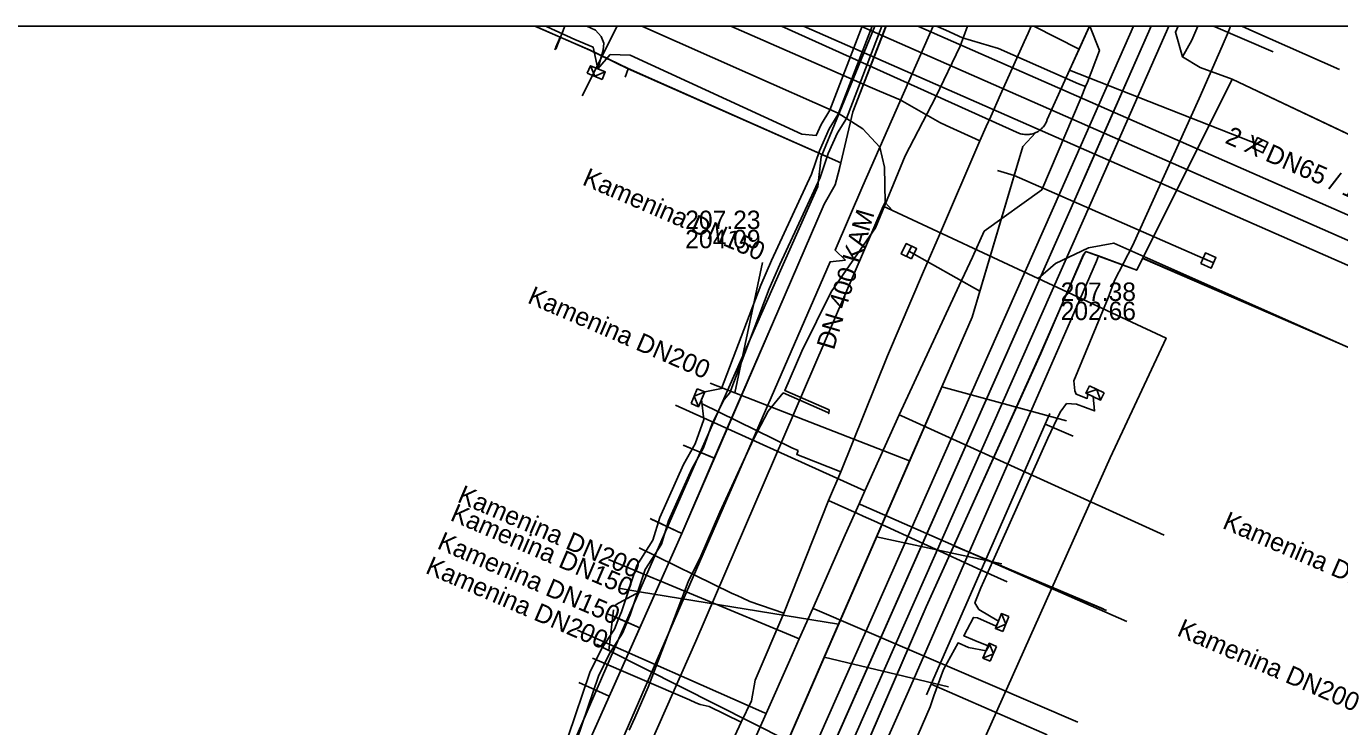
# Model space of a CAD drawing. Extents: x -596024 to -594475, y -1163820 to -1161957.
# Drawn here: x -595846.1 to -595789, y -1161987.3 to -1161956.9 of the extents above; entities that cross this region are included whole.
import ezdxf

# ---------------------------------------------------------------- set-up
doc = ezdxf.new("R2010")
doc.units = 0
for name, color, linetype in [('31', 7, 'Continuous'), ('Level 1', 7, 'Continuous'), ('Vrstva 1', 7, 'Continuous'), ('Vrstva 10', 7, 'Continuous'), ('Vrstva 12', 7, 'Continuous'), ('Vrstva 13', 7, 'Continuous'), ('Vrstva 16', 7, 'Continuous'), ('Vrstva 25', 7, 'Continuous'), ('Vrstva 3', 7, 'Continuous'), ('Vrstva 37', 7, 'Continuous'), ('Vrstva 38', 7, 'Continuous'), ('Vrstva 41', 7, 'Continuous'), ('Vrstva 42', 7, 'Continuous'), ('Vrstva 43', 7, 'Continuous'), ('Vrstva 44', 7, 'Continuous'), ('Vrstva 55', 7, 'Continuous'), ('Vrstva 63', 7, 'Continuous'), ('Vrstva 9', 7, 'Continuous')]:
    doc.layers.add(name, color=color, linetype=linetype)

# ---------------------------------------------------------------- blocks, each defined once
blk = doc.blocks.new('NN630')
at = {"layer": '31'}
for points in [[(-0.003, -0.7), (-0.703, 0)], [(-0.703, -0.7), (-0.703, 0), (0.697, 0), (0.697, -0.7)], [(-0.003, -0.7), (0.697, 0)], [(-0.703, -0.7), (0.697, -0.7)]]:
    blk.add_lwpolyline(points, dxfattribs=at)

msp = doc.modelspace()

# ---------------------------------------------------------------- linework, layer by layer
at = {"layer": 'Level 1'}
msp.add_line((-595802.331, -1161956.88), (-595800.365, -1161957.873), dxfattribs=at)
for points in [[(-595857.91, -1162093.25), (-595857.56, -1162092.36), (-595828.59, -1162027.72), (-595816.316, -1162000), (-595800.5, -1161964.28), (-595800, -1161963.147), (-595797.235, -1161956.88)], [(-595799.915, -1161956.88), (-595800, -1161957.068), (-595801.75, -1161960.93)], [(-595800.778, -1161958.784), (-595792.493, -1161962.047)], [(-595861.01, -1162094.34), (-595840.98, -1162050.22), (-595835.296, -1162037.702), (-595840.98, -1162050.22), (-595820.05, -1162004.1), (-595818.268, -1162000), (-595805.02, -1161969.52), (-595802.82, -1161962.1)], [(-595803.196, -1161963.363), (-595794.753, -1161967.058)], [(-595804.684, -1161968.388), (-595807.765, -1161966.655)]]:
    msp.add_lwpolyline(points, dxfattribs=at)
at = {"layer": 'Vrstva 1'}
msp.add_line((-595802.331, -1161956.88), (-595800.365, -1161957.873), dxfattribs=at)
for points in [[(-595792.493, -1161962.047), (-595800.778, -1161958.784)], [(-595794.753, -1161967.058), (-595803.196, -1161963.363)], [(-595807.765, -1161966.655), (-595804.684, -1161968.388)]]:
    msp.add_lwpolyline(points, dxfattribs=at)
at = {"layer": 'Vrstva 10'}
for p, q in [((-595801.14, -1161963.997), (-595798, -1161956.88)), ((-595796.47, -1161956.88), (-595799.86, -1161964.563)), ((-595829.23, -1162027.437), (-595801.14, -1161963.997)), ((-595799.86, -1161964.563), (-595827.95, -1162028.003))]:
    msp.add_line(p, q, dxfattribs=at)
at = {"layer": 'Vrstva 12'}
for p, q in [((-595822.92, -1161957.36), (-595824.015, -1161956.88)), ((-595819.366, -1161956.88), (-595814.76, -1161958.92))]:
    msp.add_line(p, q, dxfattribs=at)
for points in [[(-595810.52, -1161967.04), (-595810.97, -1161966.6), (-595809.77, -1161963.81), (-595806.71, -1161956.88)], [(-595808.757, -1161956.88), (-595810.2, -1161960.6), (-595810.72, -1161962.82)], [(-595796.064, -1161956.88), (-595796.18, -1161957.14), (-595795.87, -1161958.21)], [(-595795.87, -1161958.21), (-595795.47, -1161957.48), (-595795.209, -1161956.88)], [(-595823.15, -1161957.9), (-595822.92, -1161957.36)], [(-595810.72, -1161962.82), (-595819.97, -1161958.72), (-595821.62, -1161957.92), (-595822.79, -1161957.41), (-595822.92, -1161957.36)], [(-595795.87, -1161958.21), (-595795.1, -1161958.67), (-595793.71, -1161959.18)], [(-595814.76, -1161958.92), (-595810.84, -1161960.65), (-595809.77, -1161961.34), (-595809.02, -1161962.13), (-595808.83, -1161963), (-595808.8, -1161964.53)], [(-595793.71, -1161959.18), (-595794.49, -1161960.72), (-595797.41, -1161966.57), (-595797.6, -1161966.96)], [(-595793.71, -1161959.18), (-595785.89, -1161962.89)], [(-595810.72, -1161962.82), (-595810.97, -1161963.77)], [(-595810.97, -1161963.77), (-595811.45, -1161964.61)], [(-595840.59, -1162036.78), (-595839, -1162033.08), (-595829.34, -1162011.43), (-595817.03, -1161983.59), (-595808.88, -1161964.7)], [(-595811.45, -1161964.61), (-595813.46, -1161969.27)], [(-595808.88, -1161964.7), (-595808.8, -1161964.53)], [(-595808.88, -1161964.7), (-595808.48, -1161964.88)], [(-595808.8, -1161964.53), (-595808.48, -1161964.88)], [(-595808.48, -1161964.88), (-595802.14, -1161967.84)], [(-595799.96, -1161966.5), (-595798.86, -1161966.3), (-595777.48, -1161975.8)], [(-595799.52, -1161966.86), (-595800.07, -1161966.66), (-595800.18, -1161966.82), (-595802.04, -1161971.1), (-595805.81, -1161979.45)], [(-595805.14, -1161979.73), (-595801.85, -1161972.23), (-595800.33, -1161968.75), (-595799.61, -1161967.08), (-595799.52, -1161966.86)], [(-595801.4, -1161967.18), (-595799.96, -1161966.5)], [(-595797.6, -1161966.96), (-595797.86, -1161967.48), (-595799.52, -1161966.86)], [(-595782.88, -1161975.65), (-595781.98, -1161973.73), (-595797.6, -1161966.96)], [(-595893.7, -1162090), (-595892.79, -1162089.92), (-595866.07, -1162088.08), (-595863.91, -1162086.54), (-595827.17, -1162003.84), (-595811.19, -1161967.11), (-595810.52, -1161967.04)], [(-595802.14, -1161967.84), (-595801.4, -1161967.18)], [(-595802.14, -1161967.84), (-595796.59, -1161970.43), (-595799.02, -1161975.63), (-595808.84, -1161997.57), (-595806.26, -1161998.72)], [(-595813.46, -1161969.27), (-595816.22, -1161975.64)], [(-595817.53, -1161975.1), (-595816.22, -1161975.64)], [(-595817.63, -1161978.92), (-595816.22, -1161975.64)], [(-595818.97, -1161978.29), (-595817.63, -1161978.92)], [(-595817.63, -1161978.92), (-595819.46, -1161983.02)], [(-595805.81, -1161979.45), (-595807.01, -1161982.1), (-595809.63, -1161988.17)], [(-595805.81, -1161979.45), (-595805.14, -1161979.73)], [(-595808.97, -1161988.44), (-595807.78, -1161985.76), (-595805.14, -1161979.73)], [(-595805.14, -1161979.73), (-595799.17, -1161982.26)], [(-595819.46, -1161983.02), (-595820.7, -1161982.47)], [(-595819.46, -1161983.02), (-595821.63, -1161987.88), (-595823.63, -1161992.66)]]:
    msp.add_lwpolyline(points, dxfattribs=at)
at = {"layer": 'Vrstva 13'}
for p, q in [((-595820.44, -1161956.88), (-595821.961, -1161959.907)), ((-595794.521, -1161956.88), (-595791.928, -1161957.986)), ((-595800.394, -1161959.382), (-595800.083, -1161959.502)), ((-595800.083, -1161959.502), (-595800.271, -1161959.969)), ((-595800.001, -1161959.302), (-595800.083, -1161959.502))]:
    msp.add_line(p, q, dxfattribs=at)
for points in [[(-595806.571, -1161956.88), (-595806.155, -1161957.046), (-595805.428, -1161957.382), (-595803.866, -1161957.852), (-595800.394, -1161959.382)], [(-595799.906, -1161956.88), (-595799.487, -1161957.932), (-595800.001, -1161959.302)], [(-595800.271, -1161959.969), (-595801.989, -1161963.985), (-595804.487, -1161965.787), (-595804.998, -1161966.917), (-595805.581, -1161968.137), (-595808.183, -1161973.758), (-595809.676, -1161977.07), (-595809.929, -1161977.631), (-595810.537, -1161978.979), (-595811.944, -1161982.169), (-595812.53, -1161983.497), (-595812.94, -1161984.427), (-595813.967, -1161986.738), (-595815.177, -1161989.464)], [(-595809.676, -1161977.07), (-595809.836, -1161976.997), (-595817.906, -1161973.339)], [(-595808.183, -1161973.758), (-595808.086, -1161973.803), (-595796.665, -1161978.994)], [(-595809.929, -1161977.631), (-595809.86, -1161977.661), (-595798.288, -1161982.741)], [(-595812.53, -1161983.497), (-595812.729, -1161983.409), (-595820.823, -1161980.045)], [(-595811.944, -1161982.169), (-595811.85, -1161982.211), (-595800.421, -1161987.108)], [(-595813.967, -1161986.738), (-595814.035, -1161986.708), (-595822.165, -1161983.121)]]:
    msp.add_lwpolyline(points, dxfattribs=at)
at = {"layer": 'Vrstva 16'}
msp.add_line((-595822.719, -1161956.88), (-595823.11, -1161957.87), dxfattribs=at)
for points in [[(-595815.509, -1161956.88), (-595809.45, -1161959.52), (-595809.04, -1161959.7), (-595808.15, -1161960.08), (-595806.413, -1161961.055), (-595806.14, -1161961.19)], [(-595804.41, -1161961.24), (-595804.21, -1161960.8), (-595803.783, -1161959.845), (-595802.76, -1161957.56), (-595802.58, -1161957.18), (-595802.453, -1161956.88)], [(-595789.05, -1161958.76), (-595792.82, -1161957.09), (-595793.292, -1161956.88)], [(-595815.89, -1161988.93), (-595815.05, -1161987.12), (-595814.61, -1161986.18), (-595814.45, -1161985.29), (-595813.2, -1161982.38), (-595811.26, -1161977.49), (-595810.72, -1161976.24), (-595808.69, -1161971.2), (-595807.13, -1161967.54), (-595807.028, -1161967.303), (-595806.441, -1161965.943), (-595804.68, -1161961.86), (-595804.41, -1161961.24)], [(-595806.14, -1161961.19), (-595805.03, -1161961.7), (-595804.68, -1161961.86)], [(-595816.78, -1161973.27), (-595812.857, -1161975.195), (-595812.58, -1161975.31)], [(-595801.64, -1161973.7), (-595801.84, -1161974.16), (-595804.63, -1161980.51), (-595809.29, -1161978.36)], [(-595801.84, -1161974.16), (-595800.626, -1161974.693)], [(-595812.38, -1161975.59), (-595812.64, -1161975.48), (-595812.58, -1161975.31)], [(-595810.72, -1161976.24), (-595812.38, -1161975.59)], [(-595811.26, -1161977.49), (-595810, -1161978.05)], [(-595810, -1161978.05), (-595809.75, -1161978.16), (-595809.29, -1161978.36)], [(-595819.49, -1161979.54), (-595815.474, -1161981.508), (-595815.2, -1161981.63)], [(-595804.63, -1161980.51), (-595806.8, -1161985.46), (-595807, -1161985.92)], [(-595804.63, -1161980.51), (-595803.49, -1161981.01)], [(-595813.2, -1161982.38), (-595814.68, -1161981.87), (-595815.01, -1161981.71), (-595815.2, -1161981.63)], [(-595821.51, -1161984.33), (-595817.304, -1161986.148), (-595817.03, -1161986.27)], [(-595806.8, -1161985.46), (-595801.76, -1161987.67)], [(-595817.03, -1161986.27), (-595816.84, -1161986.34), (-595816.44, -1161986.44), (-595815.05, -1161987.12)]]:
    msp.add_lwpolyline(points, dxfattribs=at)
at = {"layer": 'Vrstva 25'}
for p, q in [((-595824.007, -1161956.88), (-595822.792, -1161957.413)), ((-595808.76, -1161956.88), (-595810.199, -1161960.596)), ((-595796.064, -1161956.88), (-595796.178, -1161957.14)), ((-595796.178, -1161957.14), (-595795.872, -1161958.208)), ((-595823.1, -1161957.785), (-595822.924, -1161957.355)), ((-595822.792, -1161957.413), (-595821.623, -1161957.924)), ((-595821.623, -1161957.924), (-595819.966, -1161958.724)), ((-595795.872, -1161958.208), (-595795.101, -1161958.666)), ((-595819.966, -1161958.724), (-595820.1, -1161959.086)), ((-595819.966, -1161958.724), (-595810.724, -1161962.816)), ((-595795.101, -1161958.666), (-595793.711, -1161959.178)), ((-595793.711, -1161959.178), (-595797.862, -1161967.482)), ((-595793.711, -1161959.178), (-595785.798, -1161962.933)), ((-595810.199, -1161960.596), (-595810.781, -1161963.057)), ((-595810.781, -1161963.057), (-595810.967, -1161963.772)), ((-595810.967, -1161963.772), (-595811.45, -1161964.613)), ((-595811.45, -1161964.613), (-595816.218, -1161975.638)), ((-595800.185, -1161966.825), (-595802.036, -1161971.101)), ((-595800.07, -1161966.659), (-595800.185, -1161966.825)), ((-595797.862, -1161967.482), (-595800.07, -1161966.659)), ((-595781.979, -1161973.731), (-595797.602, -1161966.963)), ((-595802.036, -1161971.101), (-595807.014, -1161982.1)), ((-595816.218, -1161975.638), (-595817.58, -1161975.077)), ((-595816.218, -1161975.638), (-595817.632, -1161978.922)), ((-595819.007, -1161978.267), (-595817.632, -1161978.922)), ((-595817.632, -1161978.922), (-595821.633, -1161987.877)), ((-595799.317, -1161982.197), (-595805.814, -1161979.448)), ((-595807.014, -1161982.1), (-595809.781, -1161988.518)), ((-595820.835, -1161982.416), (-595819.463, -1161983.021)), ((-595822.103, -1161985.394), (-595820.788, -1161985.986))]:
    msp.add_line(p, q, dxfattribs=at)
for points in [[(-595796.064, -1161956.88), (-595796.178, -1161957.14), (-595795.872, -1161958.208), (-595795.101, -1161958.666)], [(-595795.101, -1161958.666), (-595793.711, -1161959.178), (-595785.798, -1161962.933), (-595784.664, -1161963.549), (-595782.616, -1161964.257), (-595777.837, -1161966.236), (-595774.457, -1161967.737), (-595768.247, -1161970.388), (-595760.858, -1161973.153), (-595753.896, -1161976.081), (-595753.519, -1161976.177), (-595746.888, -1161962.088), (-595743.434, -1161963.501), (-595735.034, -1161966.944), (-595733.897, -1161966.99), (-595707.889, -1161978.267), (-595695.948, -1161983.519), (-595693.233, -1161984.785), (-595692.606, -1161985.262)]]:
    msp.add_lwpolyline(points, dxfattribs=at)
at = {"layer": 'Vrstva 3'}
for p, q in [((-595792.718, -1161961.937), (-595792.268, -1161962.157)), ((-595807.874, -1161966.88), (-595807.656, -1161966.43)), ((-595794.981, -1161966.955), (-595794.525, -1161967.161))]:
    msp.add_line(p, q, dxfattribs=at)
for points in [[(-595792.827, -1161962.162), (-595792.378, -1161962.381), (-595792.159, -1161961.932), (-595792.608, -1161961.713)], [(-595807.648, -1161966.989), (-595807.431, -1161966.538), (-595807.882, -1161966.321), (-595808.099, -1161966.772)], [(-595795.084, -1161967.183), (-595794.628, -1161967.389), (-595794.422, -1161966.933), (-595794.878, -1161966.727)]]:
    msp.add_lwpolyline(points, close=True, dxfattribs=at)
at = {"layer": 'Vrstva 37'}
msp.add_line((-595761.518, -1161978.116), (-595809.858, -1161956.88), dxfattribs=at)
at = {"layer": 'Vrstva 38'}
for p, q in [((-595762.847, -1161978.625), (-595812.344, -1161956.88)), ((-595762.02, -1161976.803), (-595807.372, -1161956.88))]:
    msp.add_line(p, q, dxfattribs=at)
at = {"layer": 'Vrstva 42'}
for points in [[(-595821.28, -1161958.73), (-595821.48, -1161957.79), (-595822.28, -1161957.45), (-595823.49, -1161956.91), (-595823.556, -1161956.88)], [(-595821.753, -1161956.88), (-595821.38, -1161957.05), (-595821.14, -1161957.32), (-595821.02, -1161957.61), (-595821.05, -1161957.92), (-595821.28, -1161958.73)], [(-595821.28, -1161958.73), (-595820.739, -1161958.101), (-595819.874, -1161958.128), (-595812.418, -1161961.572), (-595811.792, -1161961.622), (-595811.583, -1161961.143), (-595811.201, -1161960.526), (-595809.793, -1161956.88)], [(-595820.413, -1161982.701), (-595820.254, -1161982.315), (-595819.594, -1161980.304), (-595818.886, -1161979.213), (-595818.589, -1161978.229), (-595817.555, -1161975.923), (-595817.052, -1161975.027), (-595816.669, -1161973.963), (-595816.774, -1161973.092), (-595816.637, -1161972.769), (-595815.902, -1161972.612), (-595814.205, -1161968.133), (-595813.736, -1161967.063), (-595811.992, -1161963.306), (-595811.65, -1161962.295), (-595811.228, -1161961.329), (-595810.841, -1161960.705), (-595809.364, -1161956.88)], [(-595808.935, -1161956.88), (-595810.481, -1161960.884), (-595810.873, -1161961.515), (-595811.266, -1161962.41), (-595811.62, -1161963.454), (-595813.37, -1161967.229), (-595813.833, -1161968.285), (-595815.543, -1161972.807), (-595815.79, -1161973.089), (-595816.312, -1161974.141), (-595816.686, -1161975.193), (-595817.197, -1161976.103), (-595818.215, -1161978.369), (-595818.52, -1161979.382), (-595819.23, -1161980.478), (-595819.88, -1161982.454), (-595820.208, -1161983.254)], [(-595793.792, -1161956.88), (-595793.881, -1161957.102), (-595794.152, -1161957.741), (-595795.151, -1161960.015), (-595798.049, -1161966.415), (-595798.832, -1161967.923), (-595799.099, -1161968.68), (-595800.592, -1161972.291), (-595800.546, -1161972.717), (-595800.492, -1161972.869), (-595800.011, -1161973.048), (-595799.981, -1161972.863), (-595799.752, -1161972.97), (-595799.692, -1161973.59), (-595800.477, -1161973.304), (-595800.913, -1161973.263), (-595801.197, -1161973.645), (-595801.724, -1161974.779), (-595803.724, -1161979.249), (-595804.633, -1161981.277), (-595804.894, -1161981.933), (-595804.729, -1161982.217), (-595803.871, -1161982.72), (-595803.975, -1161982.945), (-595804.781, -1161982.581), (-595804.963, -1161982.564), (-595805.231, -1161983.084), (-595805.379, -1161983.361), (-595804.902, -1161983.56), (-595804.287, -1161983.812), (-595804.41, -1161984.008), (-595805.179, -1161983.864), (-595805.628, -1161983.673), (-595806.263, -1161984.82), (-595806.681, -1161985.964), (-595806.846, -1161986.446), (-595809.527, -1161992.665)], [(-595822.565, -1161987.732), (-595821.628, -1161984.962), (-595821.127, -1161983.935), (-595820.564, -1161983.068), (-595820.413, -1161982.701)], [(-595820.208, -1161983.254), (-595820.779, -1161984.133), (-595821.256, -1161985.114), (-595822.192, -1161987.879)]]:
    msp.add_lwpolyline(points, dxfattribs=at)
at = {"layer": 'Vrstva 44'}
for points in [[(-595811.58, -1161962.55), (-595810.89, -1161960.903), (-595809.248, -1161956.88)], [(-595842.415, -1162033.93), (-595839.056, -1162026.457), (-595838.264, -1162024.39), (-595837.306, -1162021.717), (-595836.483, -1162019.825), (-595831.803, -1162009.993), (-595828.878, -1162003.021), (-595826.482, -1161996.984), (-595825.943, -1161995.285), (-595824.116, -1161992.127), (-595819.264, -1161980.945), (-595816.953, -1161975.663), (-595813.458, -1161967.75), (-595811.719, -1161963.84), (-595811.58, -1161962.55)]]:
    msp.add_lwpolyline(points, dxfattribs=at)
at = {"layer": 'Vrstva 55'}
msp.add_lwpolyline([(-595805.22, -1161956.88), (-595805.53, -1161957.74), (-595806.6, -1161959.94), (-595807.93, -1161962.51), (-595809.21, -1161965.63), (-595811.14, -1161968.42), (-595812.41, -1161971), (-595813.156, -1161972.705), (-595811.236, -1161973.545), (-595811.25, -1161973.71), (-595811.284, -1161973.655), (-595813.221, -1161972.808), (-595813.88, -1161973.6), (-595814.51, -1161974.82), (-595815.98, -1161977.99), (-595816.8, -1161979.9), (-595817.36, -1161981.02), (-595819.1, -1161985.6), (-595819.67, -1161986.93), (-595819.92, -1161987.46)], dxfattribs=at)
at = {"layer": 'Vrstva 63'}
msp.add_lwpolyline([(-594475.47, -1163820.23), (-596024.42, -1163820.23), (-596024.42, -1161956.88), (-594475.47, -1161956.88)], close=True, dxfattribs=at)
at = {"layer": 'Vrstva 9'}
for p, q in [((-595797.235, -1161956.88), (-595800.5, -1161964.28)), ((-595803.196, -1161963.363), (-595803.916, -1161963.149)), ((-595800.5, -1161964.28), (-595828.59, -1162027.72)), ((-595814.13, -1161967.15), (-595815.33, -1161972.81)), ((-595800.91, -1161974.02), (-595806.337, -1161972.551)), ((-595803.72, -1161980.23), (-595809.167, -1161979.061)), ((-595820.52, -1161982.02), (-595819.47, -1161981.45)), ((-595820.6, -1161982.23), (-595820.8, -1161984)), ((-595806.05, -1161985.58), (-595811.44, -1161984.29))]:
    msp.add_line(p, q, dxfattribs=at)
for points in [[(-595802.25, -1161961.5), (-595802.308, -1161961.524), (-595802.378, -1161961.548), (-595802.437, -1161961.562), (-595802.487, -1161961.572), (-595802.544, -1161961.58), (-595802.605, -1161961.585), (-595802.67, -1161961.585), (-595802.743, -1161961.58), (-595802.797, -1161961.574), (-595802.86, -1161961.561), (-595802.907, -1161961.55), (-595802.962, -1161961.532), (-595813.294, -1161956.88)], [(-595799.915, -1161956.88), (-595800.365, -1161957.873), (-595800.778, -1161958.784), (-595801.75, -1161960.93), (-595801.763, -1161960.967), (-595801.777, -1161961.007), (-595801.797, -1161961.052), (-595801.816, -1161961.091), (-595801.838, -1161961.129), (-595801.861, -1161961.167), (-595801.888, -1161961.206), (-595801.921, -1161961.247), (-595801.951, -1161961.283), (-595801.983, -1161961.316), (-595802.026, -1161961.356), (-595802.064, -1161961.387), (-595802.102, -1161961.415), (-595802.153, -1161961.449), (-595802.202, -1161961.476), (-595802.25, -1161961.5)], [(-595802.25, -1161961.5), (-595802.82, -1161962.1), (-595803.196, -1161963.363), (-595804.684, -1161968.388), (-595805.02, -1161969.52)], [(-595805.02, -1161969.52), (-595806.337, -1161972.551), (-595807.732, -1161975.759), (-595809.167, -1161979.061), (-595810.818, -1161982.86), (-595811.44, -1161984.29), (-595813.018, -1161987.921), (-595814.812, -1161992.049), (-595815.233, -1161993.021), (-595816.681, -1161996.349), (-595819.12, -1162001.96), (-595819.532, -1162002.909), (-595820.05, -1162004.1)], [(-595816.4, -1161972.39), (-595815.33, -1161972.81), (-595807.732, -1161975.759)], [(-595820.29, -1161981.31), (-595819.47, -1161981.45), (-595810.818, -1161982.86)], [(-595821.34, -1161983.73), (-595820.8, -1161984), (-595813.018, -1161987.921)]]:
    msp.add_lwpolyline(points, dxfattribs=at)

# ---------------------------------------------------------------- block references
at = {"layer": 'Vrstva 43'}
for p, xscale, yscale, rotation in [((-595821.28, -1161958.73), 0.5, 0.5, -23.00000000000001), ((-595816.774, -1161973.092), 0.5000000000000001, 0.5, -113), ((-595799.752, -1161972.971), 0.49999999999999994, 0.5000000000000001, 155), ((-595803.871, -1161982.72), 0.5, 0.4999999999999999, 68), ((-595804.41, -1161984.008), 0.5000000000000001, 0.4999999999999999, 67)]:
    msp.add_blockref('NN630', p, dxfattribs=dict(at, xscale=xscale, yscale=yscale, rotation=rotation))

# ---------------------------------------------------------------- texts
at = {"layer": 'Vrstva 12'}
for s, rotation, p in [('Kamenina DN150', 336.6749, (-595821.999, -1161963.745)), ('DN 400 KAM', 73.4681, (-595811.024, -1161970.976)), ('Kamenina DN200', 336.6749, (-595824.383, -1161968.88)), ('Kamenina DN200', 336.6749, (-595827.43, -1161977.526)), ('Kamenina DN150', 336.6749, (-595827.74, -1161978.326)), ('Kamenina DN200', 336.6749, (-595794.183, -1161978.67)), ('Kamenina DN150', 336.6749, (-595828.307, -1161979.551)), ('Kamenina DN200', 336.6749, (-595828.816, -1161980.619)), ('Kamenina DN200', 336.6749, (-595796.158, -1161983.333))]:
    msp.add_text(s, height=0.8, rotation=rotation, dxfattribs=at).set_placement(p)
for s, p in [('207.23', (-595817.483, -1161965.69)), ('204.09', (-595817.483, -1161966.522)), ('207.38', (-595801.169, -1161968.812)), ('202.66', (-595801.169, -1161969.644))]:
    msp.add_text(s, height=0.8, dxfattribs=at).set_placement(p)
at = {"layer": 'Vrstva 41'}
msp.add_text('2 X DN65 / 140', height=0.8, rotation=336.2689, dxfattribs=at).set_placement((-595794.068, -1161961.934))

doc.saveas('drawing.dxf')
